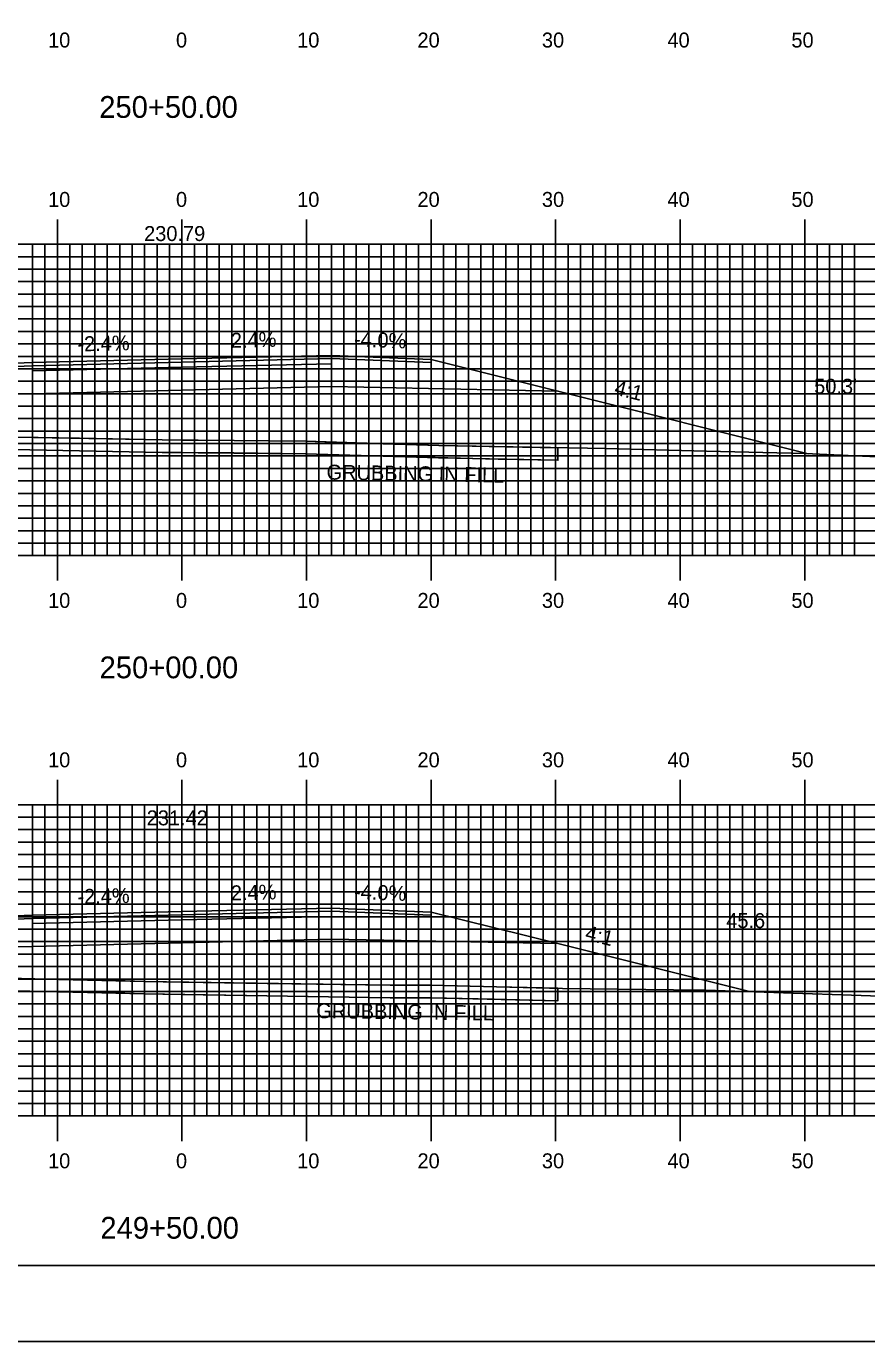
# Model space of a CAD drawing. Extents: x 1803897 to 1804240, y 442591 to 442811.
# Drawn here: x 1804050.2 to 1804117.6, y 442590.5 to 442696.2 of the extents above; entities that cross this region are included whole.
import ezdxf

# ---------------------------------------------------------------- set-up
doc = ezdxf.new("R2010")
doc.units = 0
for name, color, linetype in [('ANNOTATION', 7, 'Continuous'), ('BORDER', 7, 'Continuous'), ('D_Roadway_Centerline', 7, 'Continuous'), ('D_Roadway_Centerline_Text', 7, 'Continuous'), ('D_Roadway_Edge_Shoulder', 7, 'Continuous'), ('D_Roadway_Edge_TW', 7, 'Continuous'), ('D_Roadway_Pavement', 7, 'Continuous'), ('D_Roadway_SlopeLines', 7, 'Continuous'), ('D_Roadway_SubGrade', 7, 'Continuous'), ('D_Text_Standard', 7, 'Continuous'), ('GRUBBING IN FILL', 7, 'Continuous'), ('H_V ANNOTATION', 7, 'Continuous'), ('MAJOR', 7, 'Continuous'), ('MINOR', 7, 'Continuous'), ('PLOT BOUNDARY', 7, 'Continuous'), ('S_Roadway_Centerline', 7, 'Continuous')]:
    doc.layers.add(name, color=color, linetype=linetype)

msp = doc.modelspace()

# ---------------------------------------------------------------- linework, layer by layer
at = {"layer": 'BORDER'}
msp.add_lwpolyline([(1803913.05, 442596.67), (1804233.05, 442596.67), (1804233.05, 442806.67), (1803913.05, 442806.67)], close=True, dxfattribs=at)
at = {"layer": 'D_Roadway_Centerline'}
for points in [[(1804022.33, 442663.77), (1804030.65, 442665.85), (1804032.48, 442666.3), (1804042.65, 442668.85), (1804050.65, 442669.17), (1804062.65, 442669.46), (1804074.65, 442669.74), (1804082.65, 442669.42), (1804092.83, 442666.88), (1804112.93, 442661.85)], [(1804025.43, 442620.17), (1804030.65, 442621.47), (1804032.48, 442621.93), (1804042.65, 442624.47), (1804050.65, 442624.79), (1804062.65, 442625.08), (1804074.65, 442625.37), (1804082.65, 442625.05), (1804092.83, 442622.51), (1804108.23, 442618.66)]]:
    msp.add_lwpolyline(points, dxfattribs=at)
at = {"layer": 'D_Roadway_Edge_Shoulder'}
for points in [[(1804050.65, 442669.17), (1804042.65, 442668.85), (1804042.65, 442668.6), (1804050.65, 442668.92)], [(1804074.65, 442669.74), (1804082.65, 442669.42), (1804082.65, 442669.17), (1804074.65, 442669.49)], [(1804050.65, 442624.79), (1804042.65, 442624.47), (1804042.65, 442624.22), (1804050.65, 442624.54)], [(1804074.65, 442625.37), (1804082.65, 442625.05), (1804082.65, 442624.8), (1804074.65, 442625.12)]]:
    msp.add_lwpolyline(points, close=True, dxfattribs=at)
at = {"layer": 'D_Roadway_Edge_TW'}
for points in [[(1804050.65, 442668.92), (1804050.65, 442669.17), (1804062.65, 442669.46), (1804074.65, 442669.74), (1804074.65, 442669.49), (1804062.65, 442669.21)], [(1804050.65, 442624.54), (1804050.65, 442624.79), (1804062.65, 442625.08), (1804074.65, 442625.37), (1804074.65, 442625.12), (1804062.65, 442624.83)]]:
    msp.add_lwpolyline(points, close=True, dxfattribs=at)
at = {"layer": 'D_Roadway_Pavement'}
for points in [[(1804050.65, 442668.5), (1804050.65, 442668.92), (1804062.65, 442669.21), (1804074.65, 442669.49), (1804074.65, 442669.08), (1804062.65, 442668.79)], [(1804050.65, 442624.13), (1804050.65, 442624.54), (1804062.65, 442624.83), (1804074.65, 442625.12), (1804074.65, 442624.7), (1804062.65, 442624.41)]]:
    msp.add_lwpolyline(points, close=True, dxfattribs=at)
at = {"layer": 'D_Roadway_SlopeLines'}
for points in [[(1804082.65, 442669.42), (1804092.83, 442666.88), (1804112.93, 442661.85)], [(1804082.65, 442625.05), (1804092.83, 442622.51), (1804108.23, 442618.66)]]:
    msp.add_lwpolyline(points, dxfattribs=at)
at = {"layer": 'D_Roadway_SubGrade'}
for points in [[(1804050.65, 442666.67), (1804032.48, 442666.3), (1804042.65, 442668.85), (1804042.65, 442668.6), (1804050.65, 442668.92), (1804062.65, 442669.21), (1804074.65, 442669.49), (1804082.65, 442669.17), (1804082.65, 442669.42), (1804092.83, 442666.88), (1804074.65, 442667.24), (1804062.65, 442666.96)], [(1804050.65, 442622.29), (1804032.48, 442621.93), (1804042.65, 442624.47), (1804042.65, 442624.22), (1804050.65, 442624.54), (1804062.65, 442624.83), (1804074.65, 442625.12), (1804082.65, 442624.8), (1804082.65, 442625.05), (1804092.83, 442622.51), (1804074.65, 442622.87), (1804062.65, 442622.58)]]:
    msp.add_lwpolyline(points, close=True, dxfattribs=at)
at = {"layer": 'GRUBBING IN FILL'}
for p, q in [((1804092.83, 442662.33), (1804092.83, 442661.33)), ((1804092.83, 442662.33), (1804092.83, 442661.33)), ((1804092.83, 442618.93), (1804092.83, 442617.93)), ((1804092.83, 442618.93), (1804092.83, 442617.93))]:
    msp.add_line(p, q, dxfattribs=at)
for points in [[(1804032.48, 442663.55), (1804032.48, 442662.55), (1804036.61, 442662.47), (1804047.76, 442662.22), (1804061.06, 442661.96), (1804062.65, 442661.95), (1804062.65, 442662.95), (1804061.07, 442662.96), (1804054.42, 442663.09), (1804047.78, 442663.22), (1804040.75, 442663.38)], [(1804032.48, 442663.55), (1804032.48, 442662.55), (1804036.61, 442662.47), (1804047.76, 442662.22), (1804061.06, 442661.96), (1804062.65, 442661.95), (1804062.65, 442662.95), (1804061.07, 442662.96), (1804054.42, 442663.09), (1804047.78, 442663.22), (1804040.75, 442663.38)], [(1804066.83, 442662.91), (1804072.59, 442662.85), (1804077.93, 442662.68), (1804083.27, 442662.52), (1804089.99, 442662.39), (1804092.83, 442662.33), (1804092.83, 442661.33), (1804088.04, 442661.42), (1804077.91, 442661.68), (1804072.57, 442661.85), (1804066.81, 442661.91), (1804062.65, 442661.95), (1804062.65, 442662.95), (1804062.65, 442662.95)], [(1804066.83, 442662.91), (1804072.59, 442662.85), (1804077.93, 442662.68), (1804083.27, 442662.52), (1804089.99, 442662.39), (1804092.83, 442662.33), (1804092.83, 442661.33), (1804088.04, 442661.42), (1804077.91, 442661.68), (1804072.57, 442661.85), (1804066.81, 442661.91), (1804062.65, 442661.95), (1804062.65, 442662.95), (1804062.65, 442662.95)], [(1804032.48, 442620.19), (1804033.83, 442620.14), (1804036.53, 442620.05), (1804040.05, 442619.94), (1804048.14, 442619.75), (1804056.23, 442619.56), (1804059.61, 442619.47), (1804062.65, 442619.43), (1804062.65, 442618.43), (1804059.58, 442618.47), (1804056.21, 442618.56), (1804048.12, 442618.75), (1804040.02, 442618.94), (1804032.48, 442619.18)], [(1804032.48, 442620.19), (1804033.83, 442620.14), (1804036.53, 442620.05), (1804040.05, 442619.94), (1804048.14, 442619.75), (1804056.23, 442619.56), (1804059.61, 442619.47), (1804062.65, 442619.43), (1804062.65, 442618.43), (1804059.58, 442618.47), (1804056.21, 442618.56), (1804048.12, 442618.75), (1804040.02, 442618.94), (1804032.48, 442619.18)], [(1804062.65, 442619.43), (1804069.49, 442619.32), (1804079.37, 442619.17), (1804082.62, 442619.17), (1804087.91, 442619.05), (1804092.83, 442618.93), (1804092.83, 442617.93), (1804087.72, 442618.05), (1804082.61, 442618.17), (1804079.36, 442618.17), (1804069.47, 442618.32), (1804062.65, 442618.43)], [(1804062.65, 442619.43), (1804069.49, 442619.32), (1804079.37, 442619.17), (1804082.62, 442619.17), (1804087.91, 442619.05), (1804092.83, 442618.93), (1804092.83, 442617.93), (1804087.72, 442618.05), (1804082.61, 442618.17), (1804079.36, 442618.17), (1804069.47, 442618.32), (1804062.65, 442618.43)]]:
    msp.add_lwpolyline(points, close=True, dxfattribs=at)
for points in [[(1804032.48, 442662.55), (1804040.73, 442662.38), (1804047.76, 442662.22), (1804061.06, 442661.96), (1804072.57, 442661.85), (1804083.24, 442661.52), (1804092.83, 442661.33)], [(1804032.48, 442662.55), (1804040.73, 442662.38), (1804047.76, 442662.22), (1804061.06, 442661.96), (1804072.57, 442661.85), (1804083.24, 442661.52), (1804092.83, 442661.33)], [(1804032.48, 442619.18), (1804040.02, 442618.94), (1804056.21, 442618.56), (1804058.07, 442618.53), (1804059.58, 442618.47), (1804079.36, 442618.17), (1804081.03, 442618.17), (1804082.61, 442618.17), (1804092.83, 442617.93)], [(1804032.48, 442619.18), (1804040.02, 442618.94), (1804056.21, 442618.56), (1804058.07, 442618.53), (1804059.58, 442618.47), (1804079.36, 442618.17), (1804081.03, 442618.17), (1804082.61, 442618.17), (1804092.83, 442617.93)]]:
    msp.add_lwpolyline(points, dxfattribs=at)
at = {"layer": 'MAJOR'}
for p, q in [((1804052.65, 442680.67), (1804052.65, 442678.67)), ((1804062.65, 442680.67), (1804062.65, 442678.67)), ((1804072.65, 442680.67), (1804072.65, 442678.67)), ((1804082.65, 442680.67), (1804082.65, 442678.67)), ((1804092.65, 442680.67), (1804092.65, 442678.67)), ((1804102.65, 442680.67), (1804102.65, 442678.67)), ((1804112.65, 442680.67), (1804112.65, 442678.67)), ((1803922.65, 442678.67), (1804202.65, 442678.67)), ((1803922.65, 442678.67), (1804202.65, 442678.67)), ((1804052.65, 442653.67), (1804052.65, 442678.67)), ((1804062.65, 442653.67), (1804062.65, 442678.67)), ((1804072.65, 442653.67), (1804072.65, 442678.67)), ((1804082.65, 442653.67), (1804082.65, 442678.67)), ((1804092.65, 442653.67), (1804092.65, 442678.67)), ((1804102.65, 442653.67), (1804102.65, 442678.67)), ((1804112.65, 442653.67), (1804112.65, 442678.67)), ((1803922.65, 442673.67), (1804202.65, 442673.67)), ((1803922.65, 442668.67), (1804202.65, 442668.67)), ((1803922.65, 442663.67), (1804202.65, 442663.67)), ((1803922.65, 442658.67), (1804202.65, 442658.67)), ((1803922.65, 442653.67), (1804202.65, 442653.67)), ((1803922.65, 442653.67), (1804202.65, 442653.67)), ((1804052.65, 442651.66), (1804052.65, 442653.67)), ((1804062.65, 442651.66), (1804062.65, 442653.67)), ((1804072.65, 442651.66), (1804072.65, 442653.67)), ((1804082.65, 442651.66), (1804082.65, 442653.67)), ((1804092.65, 442651.66), (1804092.65, 442653.67)), ((1804102.65, 442651.66), (1804102.65, 442653.67)), ((1804112.65, 442651.66), (1804112.65, 442653.67)), ((1804052.65, 442635.67), (1804052.65, 442633.67)), ((1804062.65, 442635.67), (1804062.65, 442633.67)), ((1804072.65, 442635.67), (1804072.65, 442633.67)), ((1804082.65, 442635.67), (1804082.65, 442633.67)), ((1804092.65, 442635.67), (1804092.65, 442633.67)), ((1804102.65, 442635.67), (1804102.65, 442633.67)), ((1804112.65, 442635.67), (1804112.65, 442633.67)), ((1803922.65, 442633.67), (1804202.65, 442633.67)), ((1803922.65, 442633.67), (1804202.65, 442633.67)), ((1804052.65, 442608.67), (1804052.65, 442633.67)), ((1804062.65, 442608.67), (1804062.65, 442633.67)), ((1804072.65, 442608.67), (1804072.65, 442633.67)), ((1804082.65, 442608.67), (1804082.65, 442633.67)), ((1804092.65, 442608.67), (1804092.65, 442633.67)), ((1804102.65, 442608.67), (1804102.65, 442633.67)), ((1804112.65, 442608.67), (1804112.65, 442633.67)), ((1803922.65, 442628.67), (1804202.65, 442628.67)), ((1803922.65, 442623.67), (1804202.65, 442623.67)), ((1803922.65, 442618.67), (1804202.65, 442618.67)), ((1803922.65, 442613.67), (1804202.65, 442613.67)), ((1803922.65, 442608.67), (1804202.65, 442608.67)), ((1803922.65, 442608.67), (1804202.65, 442608.67)), ((1804052.65, 442606.66), (1804052.65, 442608.67)), ((1804062.65, 442606.66), (1804062.65, 442608.67)), ((1804072.65, 442606.66), (1804072.65, 442608.67)), ((1804082.65, 442606.66), (1804082.65, 442608.67)), ((1804092.65, 442606.66), (1804092.65, 442608.67)), ((1804102.65, 442606.66), (1804102.65, 442608.67)), ((1804112.65, 442606.66), (1804112.65, 442608.67))]:
    msp.add_line(p, q, dxfattribs=at)
at = {"layer": 'MINOR'}
for p, q in [((1804050.65, 442653.67), (1804050.65, 442678.67)), ((1804051.65, 442653.67), (1804051.65, 442678.67)), ((1804053.65, 442653.67), (1804053.65, 442678.67)), ((1804054.65, 442653.67), (1804054.65, 442678.67)), ((1804055.65, 442653.67), (1804055.65, 442678.67)), ((1804056.65, 442653.67), (1804056.65, 442678.67)), ((1804057.65, 442653.67), (1804057.65, 442678.67)), ((1804058.65, 442653.67), (1804058.65, 442678.67)), ((1804059.65, 442653.67), (1804059.65, 442678.67)), ((1804060.65, 442653.67), (1804060.65, 442678.67)), ((1804061.65, 442653.67), (1804061.65, 442678.67)), ((1804063.65, 442653.67), (1804063.65, 442678.67)), ((1804064.65, 442653.67), (1804064.65, 442678.67)), ((1804065.65, 442653.67), (1804065.65, 442678.67)), ((1804066.65, 442653.67), (1804066.65, 442678.67)), ((1804067.65, 442653.67), (1804067.65, 442678.67)), ((1804068.65, 442653.67), (1804068.65, 442678.67)), ((1804069.65, 442653.67), (1804069.65, 442678.67)), ((1804070.65, 442653.67), (1804070.65, 442678.67)), ((1804071.65, 442653.67), (1804071.65, 442678.67)), ((1804073.65, 442653.67), (1804073.65, 442678.67)), ((1804074.65, 442653.67), (1804074.65, 442678.67)), ((1804075.65, 442653.67), (1804075.65, 442678.67)), ((1804076.65, 442653.67), (1804076.65, 442678.67)), ((1804077.65, 442653.67), (1804077.65, 442678.67)), ((1804078.65, 442653.67), (1804078.65, 442678.67)), ((1804079.65, 442653.67), (1804079.65, 442678.67)), ((1804080.65, 442653.67), (1804080.65, 442678.67)), ((1804081.65, 442653.67), (1804081.65, 442678.67)), ((1804083.65, 442653.67), (1804083.65, 442678.67)), ((1804084.65, 442653.67), (1804084.65, 442678.67)), ((1804085.65, 442653.67), (1804085.65, 442678.67)), ((1804086.65, 442653.67), (1804086.65, 442678.67)), ((1804087.65, 442653.67), (1804087.65, 442678.67)), ((1804088.65, 442653.67), (1804088.65, 442678.67)), ((1804089.65, 442653.67), (1804089.65, 442678.67)), ((1804090.65, 442653.67), (1804090.65, 442678.67)), ((1804091.65, 442653.67), (1804091.65, 442678.67)), ((1804093.65, 442653.67), (1804093.65, 442678.67)), ((1804094.65, 442653.67), (1804094.65, 442678.67)), ((1804095.65, 442653.67), (1804095.65, 442678.67)), ((1804096.65, 442653.67), (1804096.65, 442678.67)), ((1804097.65, 442653.67), (1804097.65, 442678.67)), ((1804098.65, 442653.67), (1804098.65, 442678.67)), ((1804099.65, 442653.67), (1804099.65, 442678.67)), ((1804100.65, 442653.67), (1804100.65, 442678.67)), ((1804101.65, 442653.67), (1804101.65, 442678.67)), ((1804103.65, 442653.67), (1804103.65, 442678.67)), ((1804104.65, 442653.67), (1804104.65, 442678.67)), ((1804105.65, 442653.67), (1804105.65, 442678.67)), ((1804106.65, 442653.67), (1804106.65, 442678.67)), ((1804107.65, 442653.67), (1804107.65, 442678.67)), ((1804108.65, 442653.67), (1804108.65, 442678.67)), ((1804109.65, 442653.67), (1804109.65, 442678.67)), ((1804110.65, 442653.67), (1804110.65, 442678.67)), ((1804111.65, 442653.67), (1804111.65, 442678.67)), ((1804113.65, 442653.67), (1804113.65, 442678.67)), ((1804114.65, 442653.67), (1804114.65, 442678.67)), ((1804115.65, 442653.67), (1804115.65, 442678.67)), ((1804116.65, 442653.67), (1804116.65, 442678.67)), ((1803922.65, 442677.67), (1804202.65, 442677.67)), ((1803922.65, 442676.67), (1804202.65, 442676.67)), ((1803922.65, 442675.67), (1804202.65, 442675.67)), ((1803922.65, 442674.67), (1804202.65, 442674.67)), ((1803922.65, 442672.67), (1804202.65, 442672.67)), ((1803922.65, 442671.67), (1804202.65, 442671.67)), ((1803922.65, 442670.67), (1804202.65, 442670.67)), ((1803922.65, 442669.67), (1804202.65, 442669.67)), ((1803922.65, 442667.67), (1804202.65, 442667.67)), ((1803922.65, 442666.67), (1804202.65, 442666.67)), ((1803922.65, 442665.67), (1804202.65, 442665.67)), ((1803922.65, 442664.67), (1804202.65, 442664.67)), ((1803922.65, 442662.67), (1804202.65, 442662.67)), ((1803922.65, 442661.67), (1804202.65, 442661.67)), ((1803922.65, 442660.67), (1804202.65, 442660.67)), ((1803922.65, 442659.67), (1804202.65, 442659.67)), ((1803922.65, 442657.67), (1804202.65, 442657.67)), ((1803922.65, 442656.67), (1804202.65, 442656.67)), ((1803922.65, 442655.67), (1804202.65, 442655.67)), ((1803922.65, 442654.67), (1804202.65, 442654.67)), ((1804050.65, 442608.67), (1804050.65, 442633.67)), ((1804051.65, 442608.67), (1804051.65, 442633.67)), ((1804053.65, 442608.67), (1804053.65, 442633.67)), ((1804054.65, 442608.67), (1804054.65, 442633.67)), ((1804055.65, 442608.67), (1804055.65, 442633.67)), ((1804056.65, 442608.67), (1804056.65, 442633.67)), ((1804057.65, 442608.67), (1804057.65, 442633.67)), ((1804058.65, 442608.67), (1804058.65, 442633.67)), ((1804059.65, 442608.67), (1804059.65, 442633.67)), ((1804060.65, 442608.67), (1804060.65, 442633.67)), ((1804061.65, 442608.67), (1804061.65, 442633.67)), ((1804063.65, 442608.67), (1804063.65, 442633.67)), ((1804064.65, 442608.67), (1804064.65, 442633.67)), ((1804065.65, 442608.67), (1804065.65, 442633.67)), ((1804066.65, 442608.67), (1804066.65, 442633.67)), ((1804067.65, 442608.67), (1804067.65, 442633.67)), ((1804068.65, 442608.67), (1804068.65, 442633.67)), ((1804069.65, 442608.67), (1804069.65, 442633.67)), ((1804070.65, 442608.67), (1804070.65, 442633.67)), ((1804071.65, 442608.67), (1804071.65, 442633.67)), ((1804073.65, 442608.67), (1804073.65, 442633.67)), ((1804074.65, 442608.67), (1804074.65, 442633.67)), ((1804075.65, 442608.67), (1804075.65, 442633.67)), ((1804076.65, 442608.67), (1804076.65, 442633.67)), ((1804077.65, 442608.67), (1804077.65, 442633.67)), ((1804078.65, 442608.67), (1804078.65, 442633.67)), ((1804079.65, 442608.67), (1804079.65, 442633.67)), ((1804080.65, 442608.67), (1804080.65, 442633.67)), ((1804081.65, 442608.67), (1804081.65, 442633.67)), ((1804083.65, 442608.67), (1804083.65, 442633.67)), ((1804084.65, 442608.67), (1804084.65, 442633.67)), ((1804085.65, 442608.67), (1804085.65, 442633.67)), ((1804086.65, 442608.67), (1804086.65, 442633.67)), ((1804087.65, 442608.67), (1804087.65, 442633.67)), ((1804088.65, 442608.67), (1804088.65, 442633.67)), ((1804089.65, 442608.67), (1804089.65, 442633.67)), ((1804090.65, 442608.67), (1804090.65, 442633.67)), ((1804091.65, 442608.67), (1804091.65, 442633.67)), ((1804093.65, 442608.67), (1804093.65, 442633.67)), ((1804094.65, 442608.67), (1804094.65, 442633.67)), ((1804095.65, 442608.67), (1804095.65, 442633.67)), ((1804096.65, 442608.67), (1804096.65, 442633.67)), ((1804097.65, 442608.67), (1804097.65, 442633.67)), ((1804098.65, 442608.67), (1804098.65, 442633.67)), ((1804099.65, 442608.67), (1804099.65, 442633.67)), ((1804100.65, 442608.67), (1804100.65, 442633.67)), ((1804101.65, 442608.67), (1804101.65, 442633.67)), ((1804103.65, 442608.67), (1804103.65, 442633.67)), ((1804104.65, 442608.67), (1804104.65, 442633.67)), ((1804105.65, 442608.67), (1804105.65, 442633.67)), ((1804106.65, 442608.67), (1804106.65, 442633.67)), ((1804107.65, 442608.67), (1804107.65, 442633.67)), ((1804108.65, 442608.67), (1804108.65, 442633.67)), ((1804109.65, 442608.67), (1804109.65, 442633.67)), ((1804110.65, 442608.67), (1804110.65, 442633.67)), ((1804111.65, 442608.67), (1804111.65, 442633.67)), ((1804113.65, 442608.67), (1804113.65, 442633.67)), ((1804114.65, 442608.67), (1804114.65, 442633.67)), ((1804115.65, 442608.67), (1804115.65, 442633.67)), ((1804116.65, 442608.67), (1804116.65, 442633.67)), ((1803922.65, 442632.67), (1804202.65, 442632.67)), ((1803922.65, 442631.67), (1804202.65, 442631.67)), ((1803922.65, 442630.67), (1804202.65, 442630.67)), ((1803922.65, 442629.67), (1804202.65, 442629.67)), ((1803922.65, 442627.67), (1804202.65, 442627.67)), ((1803922.65, 442626.67), (1804202.65, 442626.67)), ((1803922.65, 442625.67), (1804202.65, 442625.67)), ((1803922.65, 442624.67), (1804202.65, 442624.67)), ((1803922.65, 442622.67), (1804202.65, 442622.67)), ((1803922.65, 442621.67), (1804202.65, 442621.67)), ((1803922.65, 442620.67), (1804202.65, 442620.67)), ((1803922.65, 442619.67), (1804202.65, 442619.67)), ((1803922.65, 442617.67), (1804202.65, 442617.67)), ((1803922.65, 442616.67), (1804202.65, 442616.67)), ((1803922.65, 442615.67), (1804202.65, 442615.67)), ((1803922.65, 442614.67), (1804202.65, 442614.67)), ((1803922.65, 442612.67), (1804202.65, 442612.67)), ((1803922.65, 442611.67), (1804202.65, 442611.67)), ((1803922.65, 442610.67), (1804202.65, 442610.67)), ((1803922.65, 442609.67), (1804202.65, 442609.67))]:
    msp.add_line(p, q, dxfattribs=at)
at = {"layer": 'PLOT BOUNDARY'}
msp.add_lwpolyline([(1803896.87, 442590.55), (1804236.87, 442590.55), (1804236.87, 442810.55), (1803896.87, 442810.55)], close=True, dxfattribs=at)
at = {"layer": 'S_Roadway_Centerline'}
for points in [[(1804005.59, 442664.19), (1804009.95, 442663.99), (1804019.39, 442663.87), (1804022.75, 442663.75), (1804040.75, 442663.38), (1804047.78, 442663.22), (1804061.07, 442662.96), (1804072.59, 442662.85), (1804083.27, 442662.52), (1804096.71, 442662.26), (1804104.76, 442662.06), (1804112.68, 442661.87), (1804121.32, 442661.47)], [(1804004.74, 442620.03), (1804015.78, 442620.02), (1804023.52, 442620.17), (1804023.56, 442620.17), (1804024.03, 442620.17), (1804031.08, 442620.16), (1804032.81, 442620.19), (1804033.02, 442620.16), (1804040.05, 442619.94), (1804056.23, 442619.56), (1804058.1, 442619.53), (1804059.61, 442619.47), (1804079.37, 442619.17), (1804081.03, 442619.17), (1804082.62, 442619.17), (1804093.2, 442618.92), (1804104.33, 442618.78), (1804104.72, 442618.78), (1804117.17, 442618.34), (1804126.83, 442618)]]:
    msp.add_lwpolyline(points, dxfattribs=at)

# ---------------------------------------------------------------- texts
at = {"layer": 'ANNOTATION'}
for s, rotation, p in [('-2.4%', 1.3748, (1804054.27, 442670.06)), ('2.4%', 1.3748, (1804066.59, 442670.35)), ('-4.0%', 357.7094, (1804076.45, 442670.47)), ('4:1', 345.9638, (1804097.3, 442666.62)), ('-2.4%', 1.3748, (1804054.27, 442625.68)), ('2.4%', 1.3748, (1804066.59, 442625.98)), ('-4.0%', 357.7094, (1804076.45, 442626.1)), ('4:1', 345.9638, (1804094.95, 442622.84))]:
    msp.add_text(s, height=1.2, rotation=rotation, dxfattribs=at).set_placement(p)
at = {"layer": 'D_Roadway_Centerline'}
for s, p in [('C', (1804062.65, 442669.46)), ('L', (1804062.65, 442669.45)), ('C', (1804062.65, 442625.08)), ('L', (1804062.65, 442625.07))]:
    msp.add_text(s, height=0.0146, dxfattribs=at).set_placement(p)
at = {"layer": 'D_Roadway_Centerline_Text'}
for s, p in [('230.79', (1804059.61, 442678.93)), ('231.42', (1804059.82, 442632.01))]:
    msp.add_text(s, height=1.2, dxfattribs=at).set_placement(p)
at = {"layer": 'D_Text_Standard'}
for s, p in [("50.3'", (1804113.41, 442666.67)), ("45.6'", (1804106.35, 442623.76))]:
    msp.add_text(s, height=1.2, dxfattribs=at).set_placement(p)
at = {"layer": 'GRUBBING IN FILL'}
for rotation, p in [(358.9706, (1804074.25, 442659.78)), (359.2219, (1804073.43, 442616.53))]:
    msp.add_text('GRUBBING IN FILL', height=1.2, rotation=rotation, dxfattribs=at).set_placement(p)
at = {"layer": 'H_V ANNOTATION'}
for s, height, p in [('10', 1.2, (1804051.9, 442694.47)), ('0', 1.2, (1804062.17, 442694.47)), ('10', 1.2, (1804071.9, 442694.47)), ('20', 1.2, (1804081.56, 442694.47)), ('30', 1.2, (1804091.55, 442694.47)), ('40', 1.2, (1804101.63, 442694.47)), ('50', 1.2, (1804111.58, 442694.47)), ('250+50.00', 1.75, (1804056.01, 442688.82)), ('10', 1.2, (1804051.9, 442681.67)), ('0', 1.2, (1804062.17, 442681.67)), ('10', 1.2, (1804071.9, 442681.67)), ('20', 1.2, (1804081.56, 442681.67)), ('30', 1.2, (1804091.55, 442681.67)), ('40', 1.2, (1804101.63, 442681.67)), ('50', 1.2, (1804111.58, 442681.67)), ('10', 1.2, (1804051.9, 442649.47)), ('0', 1.2, (1804062.17, 442649.47)), ('10', 1.2, (1804071.9, 442649.47)), ('20', 1.2, (1804081.56, 442649.47)), ('30', 1.2, (1804091.55, 442649.47)), ('40', 1.2, (1804101.63, 442649.47)), ('50', 1.2, (1804111.58, 442649.47)), ('250+00.00', 1.75, (1804056.04, 442643.82)), ('10', 1.2, (1804051.9, 442636.67)), ('0', 1.2, (1804062.17, 442636.67)), ('10', 1.2, (1804071.9, 442636.67)), ('20', 1.2, (1804081.56, 442636.67)), ('30', 1.2, (1804091.55, 442636.67)), ('40', 1.2, (1804101.63, 442636.67)), ('50', 1.2, (1804111.58, 442636.67)), ('10', 1.2, (1804051.9, 442604.47)), ('0', 1.2, (1804062.17, 442604.47)), ('10', 1.2, (1804071.9, 442604.47)), ('20', 1.2, (1804081.56, 442604.47)), ('30', 1.2, (1804091.55, 442604.47)), ('40', 1.2, (1804101.63, 442604.47)), ('50', 1.2, (1804111.58, 442604.47)), ('249+50.00', 1.75, (1804056.1, 442598.82))]:
    msp.add_text(s, height=height, dxfattribs=at).set_placement(p)

doc.saveas('drawing.dxf')
